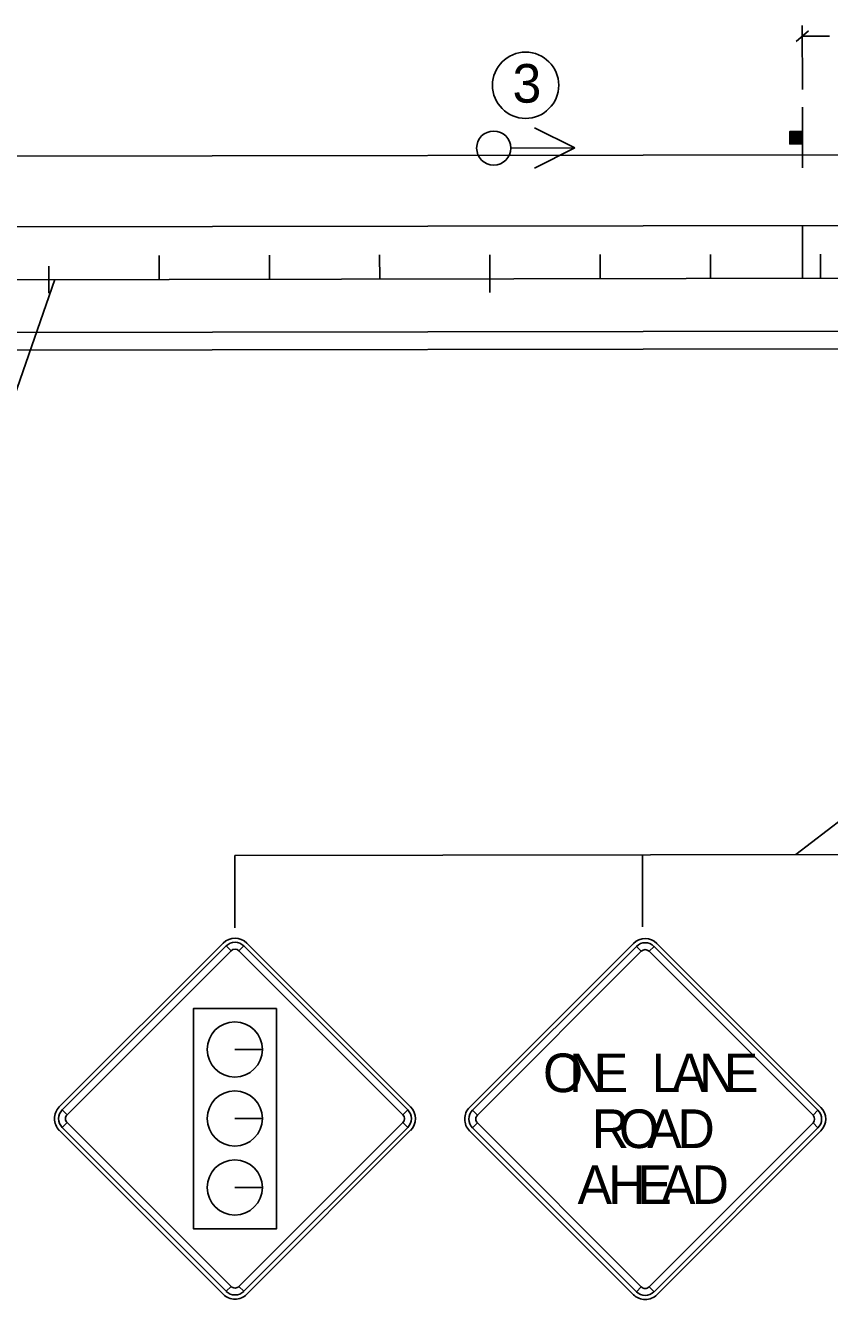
# Model space of a CAD drawing. Extents: x 16513048 to 16518780, y 7009856 to 7010869.
# Drawn here: x 16516235.5 to 16516417.8, y 7010127.1 to 7010416.1 of the extents above; entities that cross this region are included whole.
import ezdxf

# ---------------------------------------------------------------- set-up
doc = ezdxf.new("R2010")
doc.units = 0
for name, color, linetype in [('dsnNonPlotable', 7, 'Continuous'), ('dsnStdLabel', 7, 'Continuous'), ('Level 2', 7, 'Continuous'), ('PavementMarking', 7, 'Continuous'), ('SheetBorder', 7, 'Continuous'), ('tdCoTitleBlock', 7, 'Continuous')]:
    doc.layers.add(name, color=color, linetype=linetype)

msp = doc.modelspace()

# ---------------------------------------------------------------- linework, layer by layer
at = {"layer": 'dsnNonPlotable'}
for p, q in [((16513050.27, 7010352.91), (16516699.62, 7010359.27)), ((16516242.14, 7010358.48), (16516165.73, 7010138.89))]:
    msp.add_line(p, q, dxfattribs=at)
for points in [[(16513050.22, 7010380.91), (16516699.59, 7010387.27), (16518770.65, 7010388.94)], [(16518770.66, 7010372.94), (16516699.61, 7010371.27), (16513050.25, 7010364.91)], [(16518770.68, 7010348.94), (16516699.64, 7010347.27), (16513050.29, 7010340.91)], [(16518770.69, 7010344.94), (16516699.64, 7010343.27), (16513050.3, 7010336.91)]]:
    msp.add_lwpolyline(points, dxfattribs=at)
at = {"layer": 'dsnStdLabel'}
for p, q in [((16516280.32, 7010208), (16516243.14, 7010170.83)), ((16516280.98, 7010207.34), (16516282.09, 7010206.23)), ((16516283.86, 7010206.23), (16516284.97, 7010207.34)), ((16516322.81, 7010170.83), (16516285.63, 7010208)), ((16516373.35, 7010207.91), (16516336.17, 7010170.73)), ((16516374.01, 7010207.24), (16516375.12, 7010206.14)), ((16516376.89, 7010206.14), (16516378, 7010207.24)), ((16516415.84, 7010170.73), (16516378.66, 7010207.91)), ((16516289.19, 7010183.86), (16516282.93, 7010183.86)), ((16516282.93, 7010183.86), (16516289.19, 7010183.86)), ((16516244.91, 7010169.06), (16516243.81, 7010170.16)), ((16516322.14, 7010170.16), (16516321.04, 7010169.06)), ((16516337.94, 7010168.96), (16516336.84, 7010170.07)), ((16516415.17, 7010170.07), (16516414.07, 7010168.96)), ((16516243.81, 7010166.18), (16516244.91, 7010167.29)), ((16516289.19, 7010168.21), (16516282.93, 7010168.21)), ((16516282.93, 7010168.21), (16516289.19, 7010168.21)), ((16516321.04, 7010167.29), (16516322.14, 7010166.18)), ((16516336.84, 7010166.08), (16516337.94, 7010167.19)), ((16516414.07, 7010167.19), (16516415.17, 7010166.08)), ((16516243.14, 7010165.52), (16516280.32, 7010128.34)), ((16516285.63, 7010128.34), (16516322.81, 7010165.52)), ((16516336.17, 7010165.42), (16516373.35, 7010128.24)), ((16516378.66, 7010128.24), (16516415.84, 7010165.42)), ((16516289.19, 7010152.56), (16516282.93, 7010152.56)), ((16516282.93, 7010152.56), (16516289.19, 7010152.56)), ((16516282.09, 7010130.11), (16516280.98, 7010129)), ((16516284.97, 7010129), (16516283.86, 7010130.11)), ((16516375.12, 7010130.01), (16516374.01, 7010128.91)), ((16516378, 7010128.91), (16516376.89, 7010130.01))]:
    msp.add_line(p, q, dxfattribs=at)
for points in [[(16516280.98, 7010207.34), (16516243.81, 7010170.16), (16516244.91, 7010169.06), (16516282.09, 7010206.23), (16516280.98, 7010207.34)], [(16516322.14, 7010170.16), (16516284.97, 7010207.34), (16516283.86, 7010206.23), (16516321.04, 7010169.06), (16516322.14, 7010170.16)], [(16516374.01, 7010207.24), (16516336.84, 7010170.07), (16516337.94, 7010168.96), (16516375.12, 7010206.14), (16516374.01, 7010207.24)], [(16516415.17, 7010170.07), (16516378, 7010207.24), (16516376.89, 7010206.14), (16516414.07, 7010168.96), (16516415.17, 7010170.07)], [(16516292.36, 7010193.18), (16516273.6, 7010193.18), (16516273.6, 7010143.16), (16516292.36, 7010143.16), (16516292.36, 7010193.18)], [(16516243.81, 7010166.18), (16516280.98, 7010129), (16516282.09, 7010130.11), (16516244.91, 7010167.29), (16516243.81, 7010166.18)], [(16516284.97, 7010129), (16516322.14, 7010166.18), (16516321.04, 7010167.29), (16516283.86, 7010130.11), (16516284.97, 7010129)], [(16516336.84, 7010166.08), (16516374.01, 7010128.91), (16516375.12, 7010130.01), (16516337.94, 7010167.19), (16516336.84, 7010166.08)], [(16516378, 7010128.91), (16516415.17, 7010166.08), (16516414.07, 7010167.19), (16516376.89, 7010130.01), (16516378, 7010128.91)]]:
    msp.add_lwpolyline(points, close=True, dxfattribs=at)
for centre in [(16516282.93, 7010183.86), (16516282.93, 7010168.21), (16516282.93, 7010152.56)]:
    msp.add_circle(centre, 6.26, dxfattribs=at)
for centre, radius, start, end in [((16516282.98, 7010205.35), 3.76, 45, 134.9997), ((16516282.98, 7010205.35), 2.82, 45, 134.9997), ((16516376, 7010205.25), 3.76, 45, 134.9997), ((16516376, 7010205.25), 2.82, 45, 134.9997), ((16516282.98, 7010205.35), 1.25, 45, 134.9997), ((16516376, 7010205.25), 1.25, 45, 134.9997), ((16516245.8, 7010168.17), 3.76, 134.9997, 225), ((16516245.8, 7010168.17), 2.82, 134.9997, 225), ((16516320.15, 7010168.17), 2.82, 315.0002, 44.9998), ((16516320.15, 7010168.17), 3.76, 315.0002, 44.9998), ((16516338.83, 7010168.07), 3.76, 134.9997, 225), ((16516338.83, 7010168.07), 2.82, 134.9997, 225), ((16516413.18, 7010168.07), 2.82, 315.0002, 44.9998), ((16516413.18, 7010168.07), 3.76, 315.0002, 44.9998), ((16516245.8, 7010168.17), 1.25, 134.9997, 225), ((16516320.15, 7010168.17), 1.25, 315.0002, 44.9998), ((16516338.83, 7010168.07), 1.25, 134.9997, 225), ((16516413.18, 7010168.07), 1.25, 315.0002, 44.9998), ((16516282.98, 7010130.99), 2.82, 225, 315.0002), ((16516282.98, 7010130.99), 1.25, 225, 315.0002), ((16516376, 7010130.9), 2.82, 225, 315.0002), ((16516376, 7010130.9), 1.25, 225, 315.0002), ((16516282.98, 7010130.99), 3.76, 225, 315.0002), ((16516376, 7010130.9), 3.76, 225, 315.0002)]:
    msp.add_arc(centre, radius, start, end, dxfattribs=at)
at = {"layer": 'Level 2'}
for p, q in [((16516410.26, 7010412.51), (16516413, 7010414.91)), ((16516411.65, 7010401.57), (16516411.62, 7010416.12)), ((16516417.8, 7010413.72), (16516411.63, 7010413.71)), ((16516411.65, 7010383.83), (16516411.65, 7010397.6)), ((16516360.02, 7010388.35), (16516350.87, 7010392.9)), ((16516408.99, 7010389.27), (16516408.99, 7010392.06)), ((16516409.15, 7010392.06), (16516409.15, 7010389.27)), ((16516409.26, 7010389.27), (16516409.26, 7010392.06)), ((16516409.42, 7010392.06), (16516409.42, 7010389.27)), ((16516409.53, 7010389.27), (16516409.52, 7010392.06)), ((16516409.74, 7010392.06), (16516409.75, 7010389.27)), ((16516409.85, 7010389.27), (16516409.85, 7010392.06)), ((16516410.07, 7010392.06), (16516410.07, 7010389.27)), ((16516410.25, 7010389.27), (16516410.25, 7010392.06)), ((16516410.41, 7010392.06), (16516410.42, 7010389.27)), ((16516410.53, 7010389.27), (16516410.53, 7010392.06)), ((16516410.66, 7010392.06), (16516410.66, 7010389.27)), ((16516410.83, 7010389.27), (16516410.83, 7010392.06)), ((16516410.93, 7010392.06), (16516410.93, 7010389.27)), ((16516411.04, 7010389.27), (16516411.04, 7010392.06)), ((16516411.17, 7010392.06), (16516411.17, 7010389.27)), ((16516411.31, 7010389.27), (16516411.31, 7010392.06)), ((16516411.45, 7010392.06), (16516411.45, 7010389.27)), ((16516360.02, 7010388.35), (16516345.52, 7010388.32)), ((16516350.89, 7010383.76), (16516360.02, 7010388.35)), ((16516410.15, 7010228.09), (16516513.12, 7010306.91)), ((16516282.93, 7010227.87), (16516559.35, 7010228.35)), ((16516282.96, 7010211.48), (16516282.93, 7010227.87)), ((16516375.39, 7010211.65), (16516375.37, 7010228.03))]:
    msp.add_line(p, q, dxfattribs=at)
msp.add_lwpolyline([(16516411.61, 7010392.06), (16516411.61, 7010389.25), (16516408.79, 7010389.25), (16516408.79, 7010392.06)], close=True, dxfattribs=at)
for centre, radius in [((16516348.87, 7010402.57), 7.51), ((16516341.65, 7010388.32), 3.87)]:
    msp.add_circle(centre, radius, dxfattribs=at)
at = {"layer": 'PavementMarking'}
msp.add_line((16516411.68, 7010370.77), (16516411.7, 7010358.77), dxfattribs=at)
at = {"layer": 'SheetBorder'}
for p, q in [((16516265.79, 7010358.52), (16516265.78, 7010363.98)), ((16516290.79, 7010358.56), (16516290.78, 7010364.02)), ((16516315.79, 7010358.61), (16516315.78, 7010364.07)), ((16516365.79, 7010358.69), (16516365.78, 7010364.15)), ((16516390.79, 7010358.74), (16516390.78, 7010364.2)), ((16516415.79, 7010358.78), (16516415.78, 7010364.24)), ((16516240.78, 7010361.54), (16516240.79, 7010355.42)), ((16516340.78, 7010361.71), (16516340.79, 7010355.59))]:
    msp.add_line(p, q, dxfattribs=at)
at = {"layer": 'tdCoTitleBlock'}
for p, q in [((16516340.79, 7010358.65), (16516340.78, 7010364.11)), ((16516240.78, 7010361.54), (16516240.79, 7010355.42))]:
    msp.add_line(p, q, dxfattribs=at)

# ---------------------------------------------------------------- texts
at = {"layer": 'dsnStdLabel'}
for s, p in [('O', (16516352.83, 7010174.18)), ('N', (16516358.72, 7010174.18)), ('E', (16516364.35, 7010174.18)), ('L', (16516377.49, 7010174.18)), ('A', (16516382.1, 7010174.18)), ('N', (16516388.24, 7010174.18)), ('E', (16516393.86, 7010174.18)), ('R', (16516363.9, 7010161.5)), ('O', (16516370.05, 7010161.5)), ('A', (16516376.48, 7010161.5)), ('D', (16516383.32, 7010161.5)), ('A', (16516360.67, 7010148.83)), ('H', (16516367.62, 7010148.83)), ('E', (16516374.24, 7010148.83)), ('A', (16516379.6, 7010148.83)), ('D', (16516386.54, 7010148.83))]:
    msp.add_text(s, height=8.76, dxfattribs=at).set_placement(p)
at = {"layer": 'Level 2'}
msp.add_text('3', height=8.76, dxfattribs=at).set_placement((16516345.92, 7010398.62))

doc.saveas('drawing.dxf')
